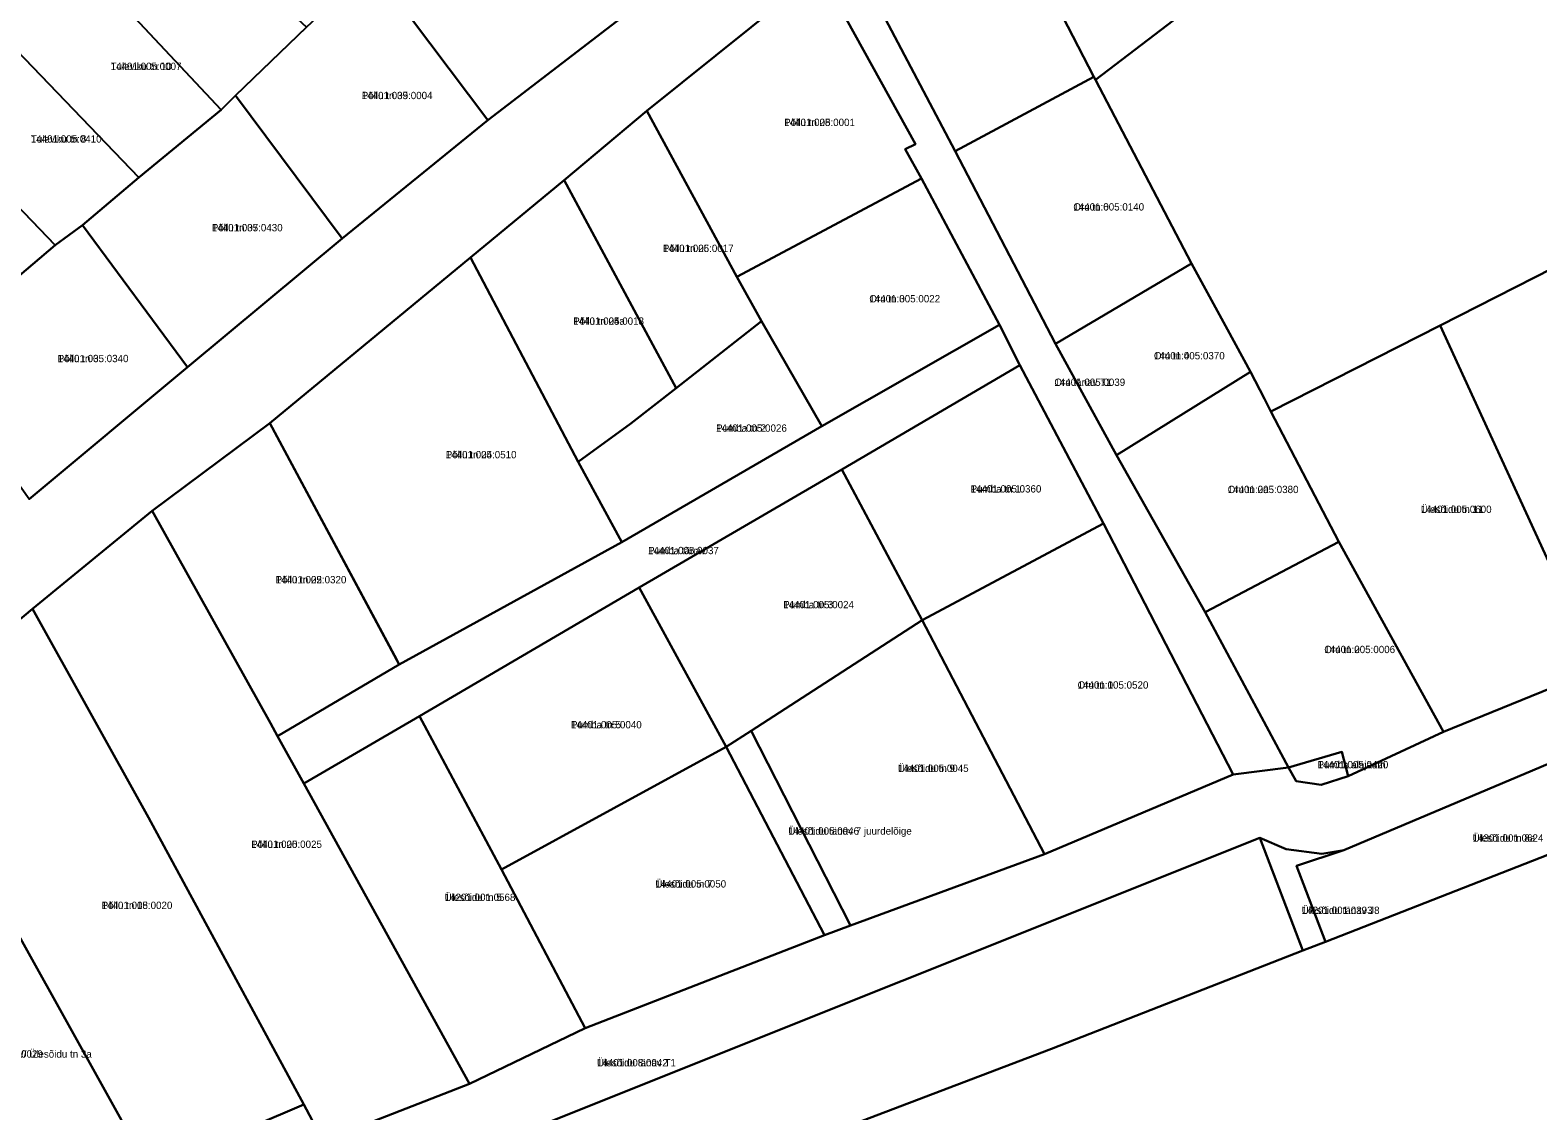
# Model space of a CAD drawing. Extents: x 640657 to 665127, y 6395726 to 6426831.
# Drawn here: x 650809.6 to 651118.5, y 6412630.2 to 6412851.6 of the extents above; entities that cross this region are included whole.
import ezdxf

# ---------------------------------------------------------------- set-up
doc = ezdxf.new("R2010")
doc.units = 0
for name, color, linetype in [('L_AADRESS', 7, 'Continuous'), ('PIIR', 7, 'Continuous'), ('TUNNUS', 7, 'Continuous')]:
    doc.layers.add(name, color=color, linetype=linetype)

msp = doc.modelspace()

# ---------------------------------------------------------------- linework, layer by layer
at = {"layer": 'PIIR'}
for points in [[(651125.47, 6412804.8), (651098.44, 6412791.06), (651063.81, 6412773.45), (651062.46, 6412776.05), (651059.6, 6412781.58), (651054.92, 6412790.21), (651047.54, 6412803.77), (651027.83, 6412841.38), (651054.65, 6412861.84), (651020.04, 6412903.56), (651031.76, 6412913.14), (651071.04, 6412887.8), (651068.11, 6412949.05), (651110.49, 6412994.23), (651113.02, 6412997.03), (651118.1, 6412996.68), (651121.96, 6412996.66)], [(650971.47, 6412863.56), (650935.96, 6412835.02), (650919, 6412820.8), (650899.8, 6412805.01), (650858.7, 6412771.04), (650834.59, 6412753.08), (650810.12, 6412733.02), (650787.5, 6412714.1)], [(650809.43, 6412755.49), (650841.85, 6412782.53), (650873.56, 6412808.84), (650903.37, 6412833.12), (650933.81, 6412856.48)], [(650869.67, 6412624.07), (650899.63, 6412635.68), (650923.33, 6412647.11), (650972.35, 6412666.17), (650977.65, 6412668.12), (651017.43, 6412682.76), (651056.04, 6412699.1), (651067.41, 6412700.48), (651069, 6412697.71), (651074.12, 6412696.95), (651079.63, 6412698.72), (651099.16, 6412707.82), (651125.2, 6412718.42)], [(651131.48, 6412705.84), (651078.72, 6412683.6), (651074.2, 6412682.8), (651066.9, 6412683.8), (651061.5, 6412686.1), (650768, 6412568.8)], [(650775.83, 6412550.52), (651018.83, 6412642.88), (651070.31, 6412663), (651074.95, 6412664.81), (651137.84, 6412689.4)]]:
    msp.add_lwpolyline(points, dxfattribs=at)
for points in [[(651020.04, 6412903.56), (651054.65, 6412861.84), (651027.83, 6412841.38), (651027.51, 6412842), (651002.89, 6412889.77)], [(650977, 6412868.75), (651002.89, 6412889.77), (651027.51, 6412842), (650999.1, 6412826.78)], [(650903.37, 6412833.12), (650879.63, 6412864.72), (650880.55, 6412865.6), (650897.27, 6412879.76), (650907.12, 6412888.13), (650933.81, 6412856.48)], [(650848.73, 6412835.25), (650819.43, 6412866.53), (650834.83, 6412881.39), (650866.25, 6412852.19), (650851.7, 6412838.15)], [(650971.47, 6412863.56), (650977, 6412868.75), (650999.1, 6412826.78), (651019.7, 6412787.3), (651032.19, 6412764.47), (651050.32, 6412732.33), (651067.41, 6412700.48), (651056.04, 6412699.1), (651029.47, 6412750.52), (651012.39, 6412782.96), (651008.19, 6412791.21), (650992.2, 6412821.17), (650988.87, 6412827.17), (650990.98, 6412828.18)], [(650803.47, 6412850.91), (650819.43, 6412866.53), (650848.73, 6412835.25), (650831.89, 6412821.36)], [(650873.56, 6412808.84), (650851.7, 6412838.15), (650866.25, 6412852.19), (650879.63, 6412864.72), (650903.37, 6412833.12)], [(650971.47, 6412863.56), (650990.98, 6412828.18), (650988.87, 6412827.17), (650992.2, 6412821.17), (650954.39, 6412801.05), (650935.96, 6412835.02)], [(650787.59, 6412835.68), (650803.47, 6412850.91), (650831.89, 6412821.36), (650820.3, 6412811.59), (650814.7, 6412807.49)], [(650999.1, 6412826.78), (651027.51, 6412842), (651027.83, 6412841.38), (651047.54, 6412803.77), (651019.7, 6412787.3)], [(650820.3, 6412811.59), (650831.89, 6412821.36), (650848.73, 6412835.25), (650851.7, 6412838.15), (650873.56, 6412808.84), (650841.85, 6412782.53)], [(650797.72, 6412793.12), (650771.66, 6412820.55), (650787.59, 6412835.68), (650814.7, 6412807.49)], [(650935.96, 6412835.02), (650954.39, 6412801.05), (650959.46, 6412791.94), (650941.93, 6412778.22), (650919, 6412820.8)], [(651156.35, 6412820.54), (651158.62, 6412821.57), (651186.24, 6412755.7), (651127.91, 6412734.55), (651124.89, 6412733.52), (651098.44, 6412791.06), (651125.47, 6412804.8), (651152.71, 6412818.6), (651154.38, 6412819.49)], [(650919, 6412820.8), (650941.93, 6412778.22), (650932.7, 6412771), (650921.9, 6412763.1), (650899.8, 6412805.01)], [(650992.2, 6412821.17), (651008.19, 6412791.21), (650971.8, 6412770.4), (650959.46, 6412791.94), (650954.39, 6412801.05)], [(650820.3, 6412811.59), (650841.85, 6412782.53), (650809.43, 6412755.49), (650788.56, 6412784.71), (650797.72, 6412793.12), (650814.7, 6412807.49)], [(650899.8, 6412805.01), (650921.9, 6412763.1), (650930.79, 6412746.65), (650885.19, 6412721.63), (650858.7, 6412771.04)], [(651019.7, 6412787.3), (651047.54, 6412803.77), (651054.92, 6412790.21), (651059.6, 6412781.58), (651032.19, 6412764.47)], [(651008.19, 6412791.21), (651012.39, 6412782.96), (650975.88, 6412761.54), (650934.37, 6412737.41), (650889.34, 6412711.04), (650865.7, 6412697.2), (650860.3, 6412706.91), (650885.19, 6412721.63), (650930.79, 6412746.65), (650971.8, 6412770.4)], [(650959.46, 6412791.94), (650971.8, 6412770.4), (650930.79, 6412746.65), (650921.9, 6412763.1), (650932.7, 6412771), (650941.93, 6412778.22)], [(651124.89, 6412733.52), (651125.2, 6412718.42), (651099.16, 6412707.82), (651077.7, 6412746.76), (651063.81, 6412773.45), (651098.44, 6412791.06)], [(650975.88, 6412761.54), (651012.39, 6412782.96), (651029.47, 6412750.52), (650992.36, 6412730.71)], [(651032.19, 6412764.47), (651059.6, 6412781.58), (651062.46, 6412776.05), (651063.81, 6412773.45), (651077.7, 6412746.76), (651050.32, 6412732.33)], [(650858.7, 6412771.04), (650884.22, 6412723.43), (650885.19, 6412721.63), (650860.3, 6412706.91), (650858.84, 6412709.56), (650834.59, 6412753.08)], [(650975.88, 6412761.54), (650992.36, 6412730.71), (650957.31, 6412708.04), (650952.17, 6412704.73), (650934.37, 6412737.41)], [(650810.12, 6412733.02), (650834.59, 6412753.08), (650858.84, 6412709.56), (650860.3, 6412706.91), (650865.7, 6412697.2), (650899.63, 6412635.68), (650869.67, 6412624.07), (650865.67, 6412631.46), (650833.84, 6412690.24)], [(650992.36, 6412730.71), (651029.47, 6412750.52), (651056.04, 6412699.1), (651017.43, 6412682.76)], [(651067.41, 6412700.48), (651050.32, 6412732.33), (651077.7, 6412746.76), (651099.16, 6412707.82), (651079.63, 6412698.72), (651078.32, 6412703.75)], [(650889.34, 6412711.04), (650934.37, 6412737.41), (650952.17, 6412704.73), (650906.16, 6412679.64)], [(650810.12, 6412733.02), (650833.84, 6412690.24), (650865.67, 6412631.46), (650834.03, 6412617.93), (650782.82, 6412709.96), (650787.5, 6412714.1)], [(650957.31, 6412708.04), (650992.36, 6412730.71), (651017.43, 6412682.76), (650977.65, 6412668.12)], [(650889.34, 6412711.04), (650906.16, 6412679.64), (650923.33, 6412647.11), (650899.63, 6412635.68), (650865.7, 6412697.2)], [(650782.82, 6412709.96), (650834.03, 6412617.93), (650837.5, 6412611.3), (650799.06, 6412596.2), (650777.6, 6412639.3), (650792, 6412647.6), (650757.9, 6412689.4)], [(650952.17, 6412704.73), (650957.31, 6412708.04), (650977.65, 6412668.12), (650972.35, 6412666.17)], [(650906.16, 6412679.64), (650952.17, 6412704.73), (650972.35, 6412666.17), (650923.33, 6412647.11)], [(651074.95, 6412664.81), (651069.02, 6412680.36), (651078.72, 6412683.6), (651131.48, 6412705.84), (651137.84, 6412689.4)], [(651079.63, 6412698.72), (651074.12, 6412696.95), (651069, 6412697.71), (651067.41, 6412700.48), (651078.32, 6412703.75)], [(650768, 6412568.8), (651061.5, 6412686.1), (651070.31, 6412663), (651018.83, 6412642.88), (650775.83, 6412550.52)], [(651074.95, 6412664.81), (651070.31, 6412663), (651061.5, 6412686.1), (651066.9, 6412683.8), (651074.2, 6412682.8), (651078.72, 6412683.6), (651069.02, 6412680.36)], [(650869.67, 6412624.07), (650837.5, 6412611.3), (650834.03, 6412617.93), (650865.67, 6412631.46)]]:
    msp.add_lwpolyline(points, close=True, dxfattribs=at)

# ---------------------------------------------------------------- texts
at = {"layer": 'L_AADRESS'}
for s, p in [('Tuleviku tn 10', (650826.1, 6412843.39)), ('Põllu tn 39', (650877.54, 6412837.42)), ('Põllu tn 28', (650964.08, 6412831.91)), ('Tuleviku tn 8', (650809.74, 6412828.52)), ('Oru tn 6', (651023.32, 6412814.6)), ('Põllu tn 37', (650846.83, 6412810.34)), ('Põllu tn 26', (650939.23, 6412806.11)), ('Oru tn 3', (650981.53, 6412795.79)), ('Põllu tn 24a', (650920.86, 6412791.2)), ('Põllu tn 35', (650815.25, 6412783.54)), ('Oru tn 4', (651039.83, 6412784.12)), ('Oru tänav T1', (651019.44, 6412778.68)), ('Pumba tn 2', (650950.13, 6412769.29)), ('Põllu tn 24', (650894.75, 6412763.85)), ('Pumba tn 1', (651002.27, 6412756.84)), ('Oru tn 2a', (651054.95, 6412756.72)), ('Ülesõidu tn 11', (651094.51, 6412752.66)), ('Pumba tänav', (650936.2, 6412744.21)), ('Põllu tn 22', (650859.89, 6412738.24)), ('Pumba tn 3', (650963.88, 6412733.13)), ('Oru tn 2', (651074.74, 6412723.94)), ('Oru tn 1', (651024.2, 6412716.67)), ('Pumba tn 5', (650920.4, 6412708.53)), ('Ülesõidu tn 9', (650987.37, 6412699.59)), ('Pumba alajaam', (651073.35, 6412700.35)), ('Põllu tn 20', (650854.88, 6412684.04)), ('Ülesõidu tänav 7 juurdelõige', (650964.91, 6412686.76)), ('Ülesõidu tn 8a', (651105.12, 6412685.32)), ('Ülesõidu tn 7', (650937.69, 6412675.92)), ('Ülesõidu tn 5', (650894.52, 6412673.17)), ('Põllu tn 18', (650824.25, 6412671.53)), ('Ülesõidu tänav J8', (651070.11, 6412670.51)), ('Põllu tn 16 // Ülesõidu tn 3a', (650797.7, 6412641.08)), ('Ülesõidu tänav T1', (650925.73, 6412639.29))]:
    msp.add_text(s, height=1.5, dxfattribs=at).set_placement(p)
at = {"layer": 'TUNNUS'}
for s, p in [('14401:005:0007', (650826.1, 6412843.39)), ('14401:005:0004', (650877.54, 6412837.42)), ('14401:005:0001', (650964.08, 6412831.91)), ('14401:005:0410', (650809.74, 6412828.52)), ('14401:005:0140', (651023.32, 6412814.6)), ('14401:005:0430', (650846.83, 6412810.34)), ('14401:005:0017', (650939.23, 6412806.11)), ('14401:005:0022', (650981.53, 6412795.79)), ('14401:005:0018', (650920.86, 6412791.2)), ('14401:005:0340', (650815.25, 6412783.54)), ('14401:005:0370', (651039.83, 6412784.12)), ('14401:005:0039', (651019.44, 6412778.68)), ('14401:005:0026', (650950.13, 6412769.29)), ('14401:005:0510', (650894.75, 6412763.85)), ('14401:005:0360', (651002.27, 6412756.84)), ('14401:005:0380', (651054.95, 6412756.72)), ('14401:005:0600', (651094.51, 6412752.66)), ('14401:005:0037', (650936.2, 6412744.21)), ('14401:005:0320', (650859.89, 6412738.24)), ('14401:005:0024', (650963.88, 6412733.13)), ('14401:005:0006', (651074.74, 6412723.94)), ('14401:005:0520', (651024.2, 6412716.67)), ('14401:005:0040', (650920.4, 6412708.53)), ('14401:005:0045', (650987.37, 6412699.59)), ('14401:005:0420', (651073.35, 6412700.35)), ('14401:005:0025', (650854.88, 6412684.04)), ('14401:005:0046', (650964.91, 6412686.76)), ('14301:001:0624', (651105.12, 6412685.32)), ('14401:005:0050', (650937.69, 6412675.92)), ('14201:001:0568', (650894.52, 6412673.17)), ('14401:005:0020', (650824.25, 6412671.53)), ('14201:001:0393', (651070.11, 6412670.51)), ('14401:005:0029', (650797.7, 6412641.08)), ('14401:008:0042', (650925.73, 6412639.29))]:
    msp.add_text(s, height=1.5, dxfattribs=at).set_placement(p)

doc.saveas('drawing.dxf')
